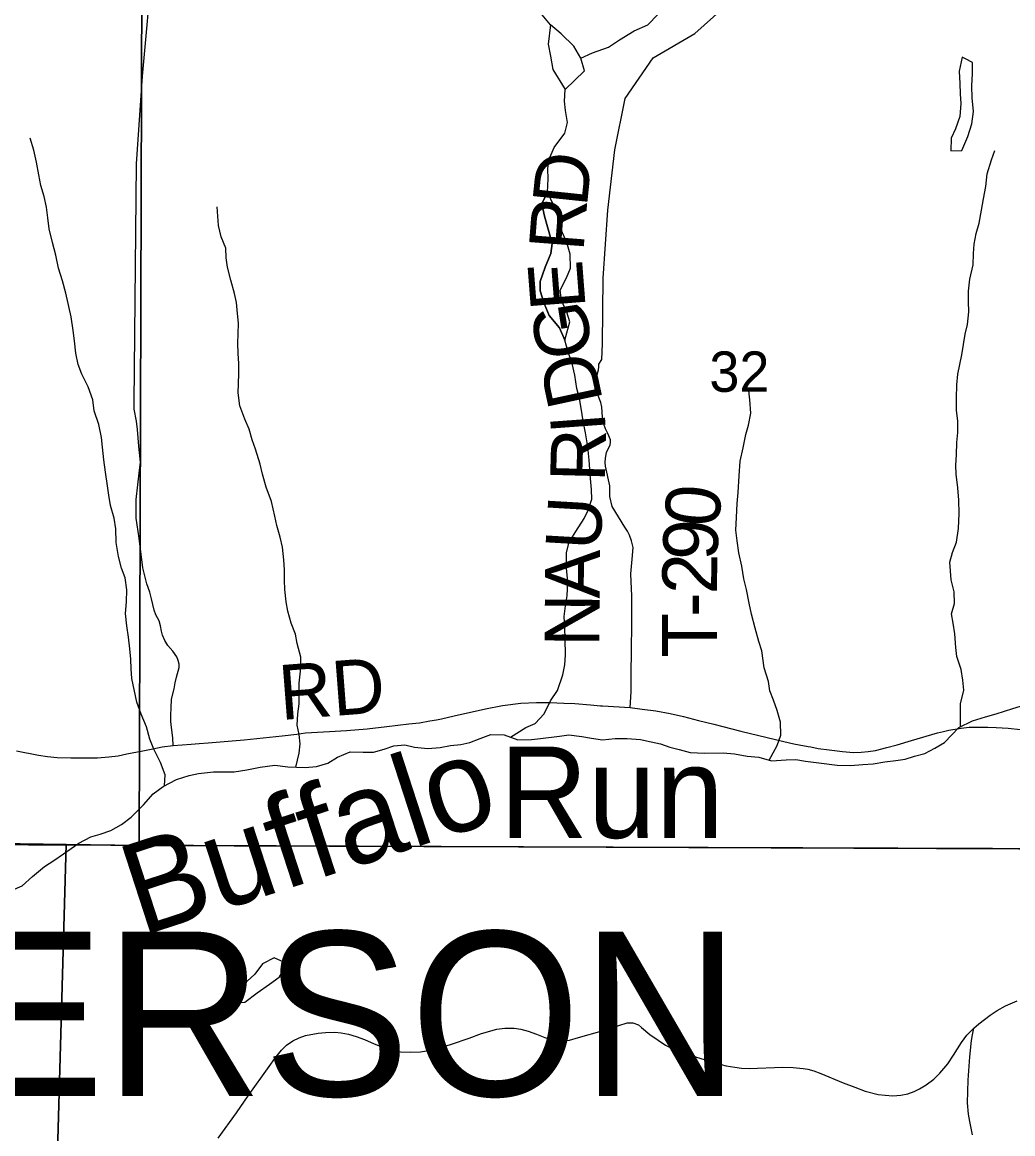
# Model space of a CAD drawing. Extents: x 0 to 34, y 0 to 22.
# Drawn here: x 5.667 to 6.694, y 18.326 to 19.478 of the extents above; entities that cross this region are included whole.
import ezdxf

# ---------------------------------------------------------------- set-up
doc = ezdxf.new("R2010")
doc.units = 0
for name, color, linetype in [('GM_X_County_Road', 7, 'Continuous'), ('GM_X_County_Road_Text', 7, 'Continuous'), ('GM_X_Minor_Lake', 7, 'Continuous'), ('GM_X_Minor_River', 7, 'Continuous'), ('GM_X_Minor_River_Text', 7, 'Continuous'), ('GM_X_Rail_Line', 7, 'Continuous'), ('GM_X_Section', 7, 'Continuous'), ('GM_X_Section_Text', 7, 'Continuous'), ('GM_X_Township_Road', 7, 'Continuous'), ('GM_X_Township_Road_Text', 7, 'Continuous'), ('GM_X_Township_Text', 7, 'Continuous')]:
    doc.layers.add(name, color=color, linetype=linetype)

msp = doc.modelspace()

# ---------------------------------------------------------------- linework, layer by layer
at = {"layer": 'GM_X_County_Road'}
for points in [[(6.102, 18.7562), (6.1151, 18.7592), (6.1477, 18.7664), (6.1653, 18.7699), (6.1843, 18.7723), (6.2004, 18.773), (6.2143, 18.7729), (6.2287, 18.7723), (6.2402, 18.7719), (6.2562, 18.7706), (6.2668, 18.7697)], [(6.2668, 18.7697), (6.2689, 18.7695), (6.2975, 18.7677), (6.31, 18.7662), (6.3242, 18.7645), (6.339, 18.7617), (6.3528, 18.7585), (6.3681, 18.7544), (6.384, 18.7504), (6.4121, 18.7433), (6.4567, 18.7325), (6.467, 18.7302), (6.4724, 18.7291), (6.482, 18.7274), (6.4848, 18.7269)], [(5.6615, 18.7228), (5.6845, 18.7185), (5.6937, 18.7169), (5.7037, 18.716), (5.718, 18.7155), (5.7337, 18.7156), (5.7456, 18.7157), (5.7571, 18.7166), (5.7669, 18.7177), (5.7759, 18.7197), (5.7923, 18.723), (5.8029, 18.7251), (5.8124, 18.7269), (5.824, 18.7286), (5.8424, 18.7299), (5.8507, 18.7304), (5.8601, 18.7312), (5.8976, 18.7342), (5.9368, 18.7384), (5.9519, 18.7403), (5.961, 18.7417), (5.9735, 18.7424), (5.9859, 18.743), (6.0034, 18.7441), (6.025, 18.7457), (6.0454, 18.7481), (6.0682, 18.7508), (6.0792, 18.7521), (6.0897, 18.7539), (6.0969, 18.7551), (6.102, 18.7562)], [(6.574, 18.7293), (6.5891, 18.7337), (6.616, 18.7416), (6.622, 18.7431), (6.6278, 18.7442), (6.6403, 18.7464), (6.6486, 18.7473), (6.6582, 18.7476), (6.6681, 18.7475), (6.6766, 18.7472), (6.6892, 18.7463), (6.7019, 18.7449), (6.7074, 18.7442), (6.7126, 18.7436)], [(6.4848, 18.7269), (6.4924, 18.7254), (6.5035, 18.7238), (6.5175, 18.7222), (6.5288, 18.7213), (6.5368, 18.7216), (6.5442, 18.7222), (6.5518, 18.7234), (6.5635, 18.7263), (6.574, 18.7293)]]:
    msp.add_lwpolyline(points, dxfattribs=at)
at = {"layer": 'GM_X_Minor_Lake'}
for points in [[(6.2149, 19.4753), (6.2126, 19.4552), (6.215, 19.443), (6.2173, 19.429), (6.2301, 19.4082)], [(6.2301, 19.4082), (6.2396, 19.4177), (6.2501, 19.4277), (6.2462, 19.4409), (6.2389, 19.4534), (6.2259, 19.4662), (6.2149, 19.4753)], [(6.6449, 19.44), (6.6414, 19.4419), (6.6385, 19.4274), (6.6389, 19.4145), (6.6393, 19.4039), (6.6401, 19.394), (6.639, 19.3804), (6.6345, 19.3675), (6.63, 19.358), (6.6297, 19.3447)], [(6.6297, 19.3447), (6.6411, 19.3451), (6.6475, 19.3596), (6.6516, 19.3729), (6.6531, 19.3854), (6.6519, 19.3998), (6.6514, 19.4123), (6.6521, 19.4248), (6.6521, 19.4362), (6.6449, 19.44)], [(6.2118, 19.3019), (6.2058, 19.2897), (6.2086, 19.2772), (6.2125, 19.2635), (6.2167, 19.2488), (6.2153, 19.2385), (6.2093, 19.2241), (6.2041, 19.2092), (6.2042, 19.1998), (6.2084, 19.1865), (6.2134, 19.174), (6.2242, 19.1612), (6.2299, 19.1487)], [(6.2299, 19.1487), (6.2348, 19.1677), (6.2317, 19.1775), (6.2263, 19.1896), (6.2248, 19.2003), (6.2315, 19.2132), (6.2357, 19.2231), (6.2352, 19.2375), (6.2318, 19.2496), (6.226, 19.2629), (6.2241, 19.2758), (6.2118, 19.3019)], [(5.9355, 18.5051), (5.9286, 18.5085), (5.9165, 18.502), (5.9085, 18.4914), (5.8968, 18.4807), (5.8885, 18.4621)], [(5.8885, 18.4621), (5.898, 18.4625), (5.9109, 18.4721), (5.9238, 18.4812), (5.9336, 18.4885), (5.9415, 18.5022), (5.9355, 18.5051)]]:
    msp.add_lwpolyline(points, dxfattribs=at)
at = {"layer": 'GM_X_Minor_River'}
for points in [[(6.1734, 18.737), (6.1893, 18.7471), (6.1991, 18.7513), (6.2082, 18.7613), (6.2149, 18.7746), (6.2221, 18.7856), (6.2277, 18.8016), (6.2299, 18.8119), (6.2306, 18.8225), (6.2301, 18.8388), (6.2296, 18.8509), (6.2292, 18.8623), (6.2306, 18.8733), (6.2321, 18.8836), (6.2327, 18.8984), (6.2315, 18.912), (6.2314, 18.9283), (6.2343, 18.9393), (6.2411, 18.9504), (6.2498, 18.9637), (6.2542, 18.9732), (6.2576, 18.9839), (6.2575, 18.9937), (6.2563, 19.0051), (6.2551, 19.0241), (6.2534, 19.0381), (6.2511, 19.0525), (6.2487, 19.065), (6.2467, 19.0779), (6.2448, 19.0881), (6.242, 19.0983), (6.24, 19.1124), (6.2373, 19.1245), (6.2331, 19.1362), (6.2299, 19.1487), (6.2242, 19.1612), (6.2134, 19.174), (6.2084, 19.1865), (6.2042, 19.1998), (6.2041, 19.2092), (6.2093, 19.2241), (6.2153, 19.2385), (6.2167, 19.2488), (6.2125, 19.2635), (6.2086, 19.2772), (6.2058, 19.2897), (6.2118, 19.3019), (6.2125, 19.3159), (6.2121, 19.3261), (6.2131, 19.3356), (6.2187, 19.3482), (6.2297, 19.3631), (6.2326, 19.3741), (6.2306, 19.3866), (6.2294, 19.3961), (6.2301, 19.4082), (6.2396, 19.4177), (6.2501, 19.4277), (6.2462, 19.4409), (6.2583, 19.4463), (6.275, 19.4521), (6.2864, 19.4598), (6.3015, 19.469), (6.3159, 19.4755), (6.326, 19.4862)], [(6.2462, 19.4409), (6.2389, 19.4534), (6.2259, 19.4662), (6.2149, 19.4753), (6.2064, 19.4858)], [(5.8148, 18.6866), (5.8156, 18.698), (5.8106, 18.7109), (5.8037, 18.7245), (5.7998, 18.7351), (5.7963, 18.7479), (5.7909, 18.7608), (5.7863, 18.7733), (5.7812, 18.7979), (5.7803, 18.8078), (5.7799, 18.818), (5.7791, 18.8286), (5.7775, 18.8408), (5.7759, 18.8525), (5.7746, 18.8654), (5.7757, 18.8772), (5.776, 18.8897), (5.774, 18.9022), (5.7705, 18.9124), (5.7674, 18.9242), (5.7647, 18.9389), (5.7646, 18.953), (5.7626, 18.9639), (5.7591, 18.9772), (5.7571, 18.9878), (5.7559, 18.9977), (5.7539, 19.0117), (5.752, 19.0246), (5.7507, 19.0375), (5.7495, 19.0477), (5.7468, 19.061), (5.7421, 19.0753), (5.7405, 19.0867), (5.7359, 19.1003), (5.7293, 19.1132), (5.7255, 19.1234), (5.7231, 19.1352), (5.7215, 19.1477), (5.7203, 19.1587), (5.7183, 19.1727), (5.7125, 19.1973), (5.7093, 19.2102), (5.7051, 19.223), (5.7023, 19.2367), (5.6988, 19.2499), (5.6953, 19.264), (5.6941, 19.2753), (5.6925, 19.2863), (5.6902, 19.2973), (5.6867, 19.3087), (5.6847, 19.32), (5.6823, 19.3329), (5.6796, 19.3454), (5.6757, 19.3579)], [(6.6396, 18.7477), (6.6398, 18.7717), (6.6432, 18.7857), (6.6423, 18.796), (6.6404, 18.8073), (6.6361, 18.8206), (6.6349, 18.83), (6.6337, 18.8441), (6.6321, 18.8551), (6.6305, 18.8649), (6.6334, 18.8756), (6.633, 18.8877), (6.6299, 18.9002), (6.6286, 18.9184), (6.6316, 18.9283), (6.6357, 18.9393), (6.6375, 18.9533), (6.6382, 18.9689), (6.6381, 18.9826), (6.6368, 18.9955), (6.6352, 19.0095), (6.6348, 19.019), (6.6355, 19.0296), (6.6361, 19.0425), (6.6368, 19.0527), (6.6368, 19.0645), (6.6355, 19.0759), (6.6355, 19.0884), (6.6358, 19.1024), (6.6368, 19.1134), (6.639, 19.1233), (6.6412, 19.1332), (6.6445, 19.1548), (6.6471, 19.1647), (6.6485, 19.178), (6.6481, 19.1886), (6.648, 19.1992), (6.6495, 19.2118), (6.6528, 19.2266), (6.6531, 19.2383), (6.6538, 19.2482), (6.656, 19.2592), (6.659, 19.2699), (6.6615, 19.2832), (6.6637, 19.2949), (6.6659, 19.3079), (6.6673, 19.3211), (6.6718, 19.3356), (6.6752, 19.3451)], [(5.951, 18.7061), (5.9544, 18.7205), (5.9555, 18.73), (5.9543, 18.7399), (5.9523, 18.7494), (5.953, 18.7611), (5.9545, 18.7717), (5.9543, 18.793), (5.9558, 18.8055), (5.9561, 18.8199), (5.9525, 18.8343), (5.9506, 18.8438), (5.9463, 18.8551), (5.9428, 18.8676), (5.9409, 18.8775), (5.9397, 18.89), (5.9392, 18.8999), (5.9391, 18.9105), (5.9387, 18.9207), (5.9371, 18.934), (5.9347, 18.9442), (5.9312, 18.9563), (5.9293, 18.9662), (5.9258, 18.9813), (5.9203, 18.9961), (5.9165, 19.0097), (5.9141, 19.0199), (5.9091, 19.0355), (5.9056, 19.0453), (5.9025, 19.0563), (5.8982, 19.0665), (5.8928, 19.0805), (5.8912, 19.0938), (5.8915, 19.1033), (5.8919, 19.1139), (5.8918, 19.1245), (5.8913, 19.1347), (5.8909, 19.1454), (5.8912, 19.1552), (5.8915, 19.1662), (5.8907, 19.1761), (5.8895, 19.1875), (5.8875, 19.1969), (5.8836, 19.2106), (5.8801, 19.2242), (5.8789, 19.234), (5.8785, 19.2439), (5.8735, 19.2556), (5.8707, 19.2674), (5.8703, 19.2772), (5.8695, 19.2867)], [(6.4414, 18.7134), (6.4499, 18.7283), (6.4536, 18.739), (6.4531, 18.7526), (6.4496, 18.7647), (6.4458, 18.7753), (6.4423, 18.7852), (6.4407, 18.7946), (6.4364, 18.809), (6.4337, 18.8265), (6.4306, 18.8363), (6.4271, 18.8499), (6.4232, 18.8647), (6.4208, 18.8761), (6.4181, 18.8901), (6.4153, 18.9011), (6.4133, 18.9143), (6.4102, 18.928), (6.4082, 18.9405), (6.407, 18.9515), (6.4077, 18.9648), (6.4084, 18.9792), (6.4094, 18.9906), (6.4105, 19.008), (6.4115, 19.0232), (6.4144, 19.0369), (6.4174, 19.0509), (6.42, 19.0604), (6.4226, 19.073), (6.4213, 19.0866), (6.4201, 19.0995)], [(6.0209, 18.7214), (6.0315, 18.7214), (6.0425, 18.7245), (6.0527, 18.728), (6.0641, 18.7292), (6.074, 18.7266), (6.0877, 18.7252), (6.1006, 18.7264), (6.1112, 18.7284), (6.1218, 18.7296), (6.1313, 18.7316), (6.1419, 18.7358), (6.1529, 18.7397), (6.1669, 18.7394), (6.181, 18.7342), (6.1951, 18.7346), (6.2046, 18.7358), (6.2243, 18.7382), (6.2338, 18.7394), (6.2474, 18.7376), (6.2573, 18.7362), (6.2687, 18.7344), (6.282, 18.7356), (6.2942, 18.7357), (6.3082, 18.7346), (6.3192, 18.7324), (6.3288, 18.7302), (6.3386, 18.7268), (6.3482, 18.7242), (6.3596, 18.7213), (6.3748, 18.7206), (6.3937, 18.7208), (6.4055, 18.7197), (6.4188, 18.7175), (6.4306, 18.7164), (6.4439, 18.7127), (6.4591, 18.7136), (6.469, 18.714), (6.4792, 18.7122), (6.4929, 18.7104), (6.5119, 18.7082), (6.5256, 18.7076), (6.5385, 18.7088), (6.5491, 18.7096), (6.5612, 18.7116), (6.5726, 18.7128), (6.5825, 18.7144), (6.592, 18.7175), (6.6026, 18.7202), (6.6132, 18.7256), (6.623, 18.7317), (6.6381, 18.747), (6.6521, 18.7539), (6.6657, 18.7582), (6.6767, 18.7613), (6.6938, 18.7667), (6.7063, 18.7706)], [(5.6569, 18.5786), (5.6675, 18.5829), (5.6781, 18.5928), (5.6906, 18.6031), (5.7004, 18.6092), (5.7102, 18.6161), (5.7261, 18.6272), (5.7386, 18.6338), (5.7484, 18.6365), (5.7594, 18.6404), (5.7704, 18.6465), (5.7802, 18.6542), (5.793, 18.6671), (5.8032, 18.6782), (5.8134, 18.6859), (5.8274, 18.6932), (5.8403, 18.6974), (5.8502, 18.6994), (5.8657, 18.701), (5.887, 18.7011), (5.9003, 18.7031), (5.9139, 18.7059), (5.9291, 18.7079), (5.9428, 18.7064), (5.9606, 18.7058), (5.9724, 18.7066), (5.9841, 18.7101), (5.994, 18.7162), (6.0072, 18.722), (6.0209, 18.7214)]]:
    msp.add_lwpolyline(points, dxfattribs=at)
at = {"layer": 'GM_X_Rail_Line'}
for points in [[(5.4171, 18.6266), (7.3845, 18.6186), (7.3876, 18.6186), (7.7217, 18.6188), (7.7247, 18.6188), (7.7665, 18.6188), (7.7949, 18.6196), (7.7955, 18.662), (7.7955, 18.6643), (7.8036, 19.6113), (7.8037, 19.6169), (7.8038, 19.6317), (8.8143, 19.6303), (8.8149, 19.7665), (8.8193, 20.9), (4.5874, 20.9)], [(8.9, 14.624), (8.9, 20.9), (8.8193, 20.9), (8.8149, 19.7665), (8.8143, 19.6303), (7.8038, 19.6317), (7.8037, 19.6169), (7.8036, 19.6113), (7.7955, 18.6643), (7.7955, 18.662), (7.7949, 18.6196), (7.7665, 18.6188), (7.7247, 18.6188), (7.7217, 18.6188), (7.3876, 18.6186), (7.3845, 18.6186), (5.4171, 18.6266)]]:
    msp.add_lwpolyline(points, dxfattribs=at)
at = {"layer": 'GM_X_Section'}
for points in [[(5.7918, 19.6342), (5.7885, 18.6247), (5.7131, 18.626), (4.5473, 18.6426), (4.5644, 19.6379)], [(5.7918, 19.6342), (6.8002, 19.6351), (6.7897, 18.6209), (6.7712, 18.6214), (5.7885, 18.6247)], [(5.7131, 18.626), (5.685, 17.6333), (4.5464, 17.6585), (4.5407, 18.3336), (4.5473, 18.6426)], [(5.7885, 18.6247), (6.7712, 18.6214), (6.7568, 17.6224), (5.685, 17.6333), (5.7131, 18.626)]]:
    msp.add_lwpolyline(points, close=True, dxfattribs=at)
at = {"layer": 'GM_X_Township_Road'}
for points in [[(5.7834, 19.0837), (5.786, 19.3314), (5.7922, 19.4222), (5.8028, 19.5407)], [(6.2975, 18.7677), (6.2984, 18.7839), (6.2986, 18.7923), (6.2984, 18.8003), (6.2989, 18.8291), (6.2992, 18.8526), (6.2991, 18.8831), (6.298, 18.9065), (6.2994, 18.9214), (6.3004, 18.9335), (6.2988, 18.9405), (6.2967, 18.9466), (6.2947, 18.9507), (6.2919, 18.9547), (6.2789, 18.9763), (6.2764, 18.9866), (6.2764, 18.9977), (6.272, 19.0178), (6.2717, 19.0219), (6.2718, 19.0264), (6.2729, 19.0322), (6.2766, 19.0401), (6.2771, 19.0425), (6.2771, 19.0453), (6.2744, 19.0519), (6.272, 19.0566), (6.2703, 19.0614), (6.2687, 19.0687), (6.2682, 19.0791), (6.2671, 19.084), (6.2641, 19.0919), (6.2628, 19.0955), (6.2624, 19.0975), (6.2623, 19.1007), (6.2631, 19.1126), (6.2645, 19.1178), (6.2649, 19.1209), (6.2651, 19.1236), (6.2682, 19.1286), (6.2688, 19.1446), (6.2693, 19.2129), (6.2744, 19.2832), (6.2814, 19.3459), (6.2922, 19.3991), (6.3213, 19.4413), (6.3644, 19.4665), (6.4158, 19.5127)], [(5.8261, 18.7933), (5.8274, 18.7993), (5.83, 18.8093), (5.83, 18.8129), (5.8292, 18.8167), (5.8276, 18.8203), (5.8234, 18.8261), (5.8184, 18.8322), (5.8151, 18.8371), (5.813, 18.8427), (5.8118, 18.8469), (5.8108, 18.8523), (5.8093, 18.8575), (5.806, 18.8637), (5.8041, 18.8688), (5.8015, 18.8805), (5.7996, 18.8872), (5.7966, 18.8959), (5.7926, 18.9126), (5.7888, 18.9432), (5.7857, 18.9642), (5.7855, 18.9745), (5.7855, 18.9835), (5.7891, 19.0139), (5.7899, 19.0222), (5.7883, 19.0386), (5.7869, 19.0559), (5.7858, 19.0645), (5.7834, 19.0771), (5.7834, 19.0837)], [(5.824, 18.7286), (5.8235, 18.7365), (5.8223, 18.747), (5.8214, 18.7533), (5.8215, 18.7601), (5.8217, 18.7673), (5.8223, 18.7765), (5.8248, 18.7872), (5.8261, 18.7933)], [(6.6535, 18.4354), (6.6586, 18.44), (6.6703, 18.4491), (6.6776, 18.4539), (6.6862, 18.4585), (6.6984, 18.4638)], [(5.8704, 18.3213), (5.8895, 18.3476), (5.9016, 18.3654), (5.9234, 18.3958), (5.9291, 18.4039), (5.936, 18.4126), (5.9413, 18.4177), (5.9478, 18.4223), (5.9544, 18.4255), (5.9611, 18.428), (5.9741, 18.4302), (5.9819, 18.431), (5.9914, 18.4312), (5.998, 18.4307), (6.0055, 18.4292), (6.0136, 18.4269), (6.0223, 18.4237), (6.0323, 18.4192), (6.042, 18.4154), (6.0505, 18.4127), (6.0593, 18.4108), (6.0695, 18.4106), (6.0802, 18.411), (6.0906, 18.4127), (6.1011, 18.4153), (6.1124, 18.419), (6.1307, 18.4252), (6.1435, 18.43), (6.1594, 18.4344), (6.1676, 18.4355), (6.1771, 18.4354), (6.1842, 18.4343), (6.1918, 18.4323), (6.2004, 18.4292), (6.209, 18.4259), (6.2158, 18.4235), (6.2213, 18.4225), (6.227, 18.4224), (6.2347, 18.4231), (6.2439, 18.4257), (6.2684, 18.4327), (6.2943, 18.441), (6.3003, 18.4409), (6.3059, 18.4388), (6.3093, 18.4363), (6.3179, 18.4289), (6.3264, 18.4229), (6.334, 18.4179), (6.3421, 18.414), (6.3582, 18.4078), (6.3866, 18.3991), (6.397, 18.3963), (6.4058, 18.3951), (6.4128, 18.3941), (6.4208, 18.3937), (6.4557, 18.3949), (6.4664, 18.3948), (6.4767, 18.3937), (6.4817, 18.3929), (6.4877, 18.3911), (6.4951, 18.3884), (6.5183, 18.3788), (6.5301, 18.3742), (6.5409, 18.3702), (6.5543, 18.3668), (6.5617, 18.3659), (6.5696, 18.3654), (6.5779, 18.3659), (6.5853, 18.3674), (6.5917, 18.3698), (6.5971, 18.3727), (6.6043, 18.3768), (6.6122, 18.3826), (6.6184, 18.3887), (6.6265, 18.3985), (6.6326, 18.4074), (6.6409, 18.4206), (6.6464, 18.4281), (6.6535, 18.4354)], [(6.652, 18.325), (6.6493, 18.3388), (6.648, 18.3464), (6.6471, 18.3582), (6.6478, 18.3815), (6.6494, 18.4057), (6.6513, 18.4228), (6.6521, 18.4286), (6.6535, 18.4354)]]:
    msp.add_lwpolyline(points, dxfattribs=at)

# ---------------------------------------------------------------- texts
at = {"layer": 'GM_X_County_Road_Text'}
msp.add_text('RD', height=0.05682, rotation=4.3991, dxfattribs=at).set_placement((5.9356, 18.7548))
at = {"layer": 'GM_X_Minor_River_Text'}
for s, rotation, p in [('Buffalo', 18.0015, (5.7905, 18.5304)), ('Run', 0.0001, (6.1622, 18.6326))]:
    msp.add_text(s, height=0.09469, rotation=rotation, dxfattribs=at).set_placement(p)
at = {"layer": 'GM_X_Section_Text'}
msp.add_text('32', height=0.04186, rotation=0, dxfattribs=at).set_placement((6.3795, 19.095))
at = {"layer": 'GM_X_Township_Road_Text'}
for s, rotation, p in [('D', 84.0368, (6.2525, 19.2858)), ('R', 85.648, (6.249, 19.2397)), ('E', 94.4401, (6.2514, 19.1821)), ('G', 99.0132, (6.2591, 19.1339)), ('D', 102.1433, (6.2694, 19.0858)), ('I', 94.1885, (6.2724, 19.0541)), ('R', 88.4378, (6.2712, 19.0012)), ('0', 84.8409, (6.389, 18.9538)), ('U', 86.665, (6.2663, 18.9299)), ('9', 87.9804, (6.3878, 18.9197)), ('A', 89.3953, (6.2658, 18.8807)), ('2', 89.2662, (6.3873, 18.885)), ('-', 89.8517, (6.3873, 18.8618)), ('N', 89.592, (6.2655, 18.8307)), ('T', 90.0043, (6.3873, 18.8194))]:
    msp.add_text(s, height=0.0568, rotation=rotation, dxfattribs=at).set_placement(p)
at = {"layer": 'GM_X_Township_Text'}
msp.add_text('JEFFERSON', height=0.17045, rotation=0, dxfattribs=at).set_placement((5.0561, 18.3652))

doc.saveas('drawing.dxf')
